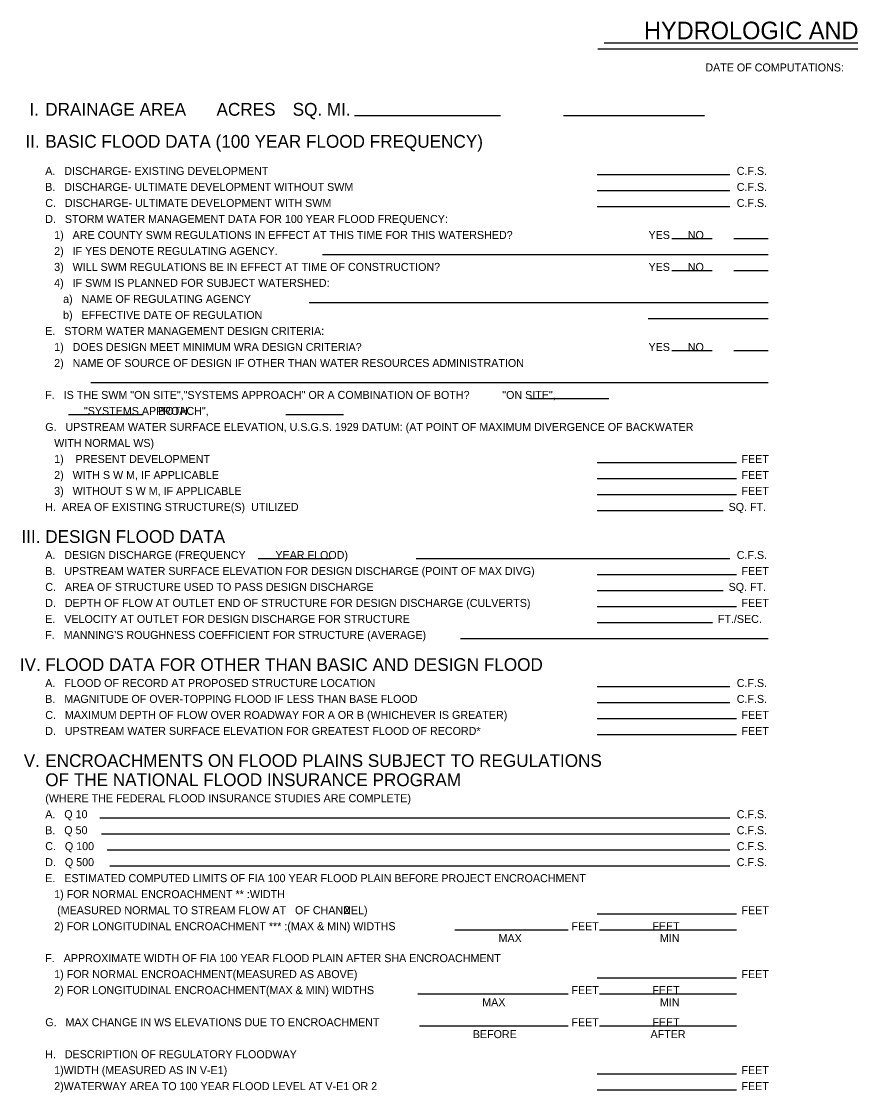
# Model space of a CAD drawing. Extents: x 3 to 31.3, y 2.1 to 20.5.
# Drawn here: x 3.01 to 13.21, y 7.36 to 20.53 of the extents above; entities that cross this region are included whole.
import ezdxf

# ---------------------------------------------------------------- set-up
doc = ezdxf.new("R2010")
doc.units = 0
doc.layers.add('G-ANNO-NOTE', color=7, linetype='Continuous')

msp = doc.modelspace()

# ---------------------------------------------------------------- linework, layer by layer
at = {"layer": 'G-ANNO-NOTE'}
for p, q in [((10.1, 20.198), (16.402, 20.198)), ((10.178, 20.27), (16.33, 20.27)), ((8.903, 19.374), (7.107, 19.374)), ((11.411, 19.374), (9.677, 19.374)), ((11.721, 18.646), (10.09, 18.646)), ((11.721, 18.449), (10.09, 18.449)), ((11.721, 18.252), (10.09, 18.252)), ((11.504, 17.858), (11.008, 17.858)), ((12.193, 17.858), (11.772, 17.858)), ((12.193, 17.661), (6.714, 17.661)), ((11.504, 17.465), (11.008, 17.465)), ((12.193, 17.465), (11.772, 17.465)), ((12.193, 17.071), (6.549, 17.071)), ((12.193, 16.874), (10.719, 16.874)), ((11.504, 16.48), (11.008, 16.48)), ((12.193, 16.48), (11.772, 16.48)), ((12.193, 16.087), (3.865, 16.087)), ((10.234, 15.89), (9.264, 15.89)), ((4.505, 15.693), (3.587, 15.693)), ((6.972, 15.693), (6.26, 15.693)), ((11.803, 15.102), (10.09, 15.102)), ((11.803, 14.905), (10.09, 14.905)), ((11.803, 14.709), (10.09, 14.709)), ((11.638, 14.512), (10.09, 14.512)), ((6.815, 13.921), (5.922, 13.921)), ((11.721, 13.921), (7.864, 13.921)), ((11.803, 13.724), (10.09, 13.724)), ((11.638, 13.528), (10.09, 13.528)), ((11.803, 13.331), (10.09, 13.331)), ((11.507, 13.134), (10.09, 13.134)), ((12.193, 12.937), (8.41, 12.937)), ((11.721, 12.346), (10.09, 12.346)), ((11.721, 12.15), (10.09, 12.15)), ((11.803, 11.953), (10.09, 11.953)), ((11.803, 11.756), (10.09, 11.756)), ((11.721, 10.732), (3.973, 10.732)), ((11.721, 10.535), (3.996, 10.535)), ((11.721, 10.339), (4.065, 10.339)), ((11.721, 10.142), (4.099, 10.142)), ((11.803, 9.551), (10.09, 9.551)), ((9.733, 9.354), (8.34, 9.354)), ((11.803, 9.354), (10.119, 9.354)), ((11.803, 8.764), (10.09, 8.764)), ((9.733, 8.567), (7.883, 8.567)), ((11.803, 8.567), (10.119, 8.567)), ((9.733, 8.173), (7.906, 8.173)), ((11.803, 8.173), (10.119, 8.173)), ((11.803, 7.583), (10.09, 7.583)), ((11.803, 7.386), (10.09, 7.386))]:
    msp.add_line(p, q, dxfattribs=at)

# ---------------------------------------------------------------- texts
for s, height, p in [('HYDROLOGIC AND HYDRAULIC DATA', 0.21654, (10.666, 20.315)), ('DATE OF COMPUTATIONS:', 0.09843, (11.421, 19.919)), ('I.  ', 0.1575, (3.108, 19.374)), ('DRAINAGE AREA', 0.15748, (3.303, 19.374)), ('                                    ACRES', 0.15748, (3.303, 19.374)), ('                                                    SQ. MI.', 0.15748, (3.303, 19.374)), ('II.  ', 0.1575, (3.059, 18.98)), ('BASIC FLOOD DATA (100 YEAR FLOOD FREQUENCY)', 0.15748, (3.303, 18.98)), ('A.   DISCHARGE- EXISTING DEVELOPMENT', 0.09843, (3.303, 18.646)), ('C.F.S.', 0.0984, (11.807, 18.646)), ('B.   DISCHARGE- ULTIMATE DEVELOPMENT WITHOUT SWM', 0.09843, (3.303, 18.449)), ('C.F.S.', 0.0984, (11.807, 18.449)), ('C.   DISCHARGE- ULTIMATE DEVELOPMENT WITH SWM', 0.09843, (3.303, 18.252)), ('C.F.S.', 0.0984, (11.807, 18.252)), ('D.   STORM WATER MANAGEMENT DATA FOR 100 YEAR FLOOD FREQUENCY:', 0.09843, (3.303, 18.055)), ('   1)   ARE COUNTY SWM REGULATIONS IN EFFECT AT THIS TIME FOR THIS WATERSHED?', 0.09843, (3.303, 17.858)), ('YES      NO     ', 0.09843, (10.722, 17.858)), ('   2)   IF YES DENOTE REGULATING AGENCY.', 0.09843, (3.303, 17.661)), ('   3)   WILL SWM REGULATIONS BE IN EFFECT AT TIME OF CONSTRUCTION?', 0.09843, (3.303, 17.465)), ('YES      NO     ', 0.09843, (10.722, 17.465)), ('   4)   IF SWM IS PLANNED FOR SUBJECT WATERSHED:', 0.09843, (3.303, 17.268)), ('      a)   NAME OF REGULATING AGENCY', 0.09843, (3.303, 17.071)), ('      b)   EFFECTIVE DATE OF REGULATION', 0.09843, (3.303, 16.874)), ('E.   STORM WATER MANAGEMENT DESIGN CRITERIA:', 0.09843, (3.303, 16.677)), ('   1)   DOES DESIGN MEET MINIMUM WRA DESIGN CRITERIA?', 0.09843, (3.303, 16.48)), ('YES      NO     ', 0.09843, (10.722, 16.48)), ('   2)   NAME OF SOURCE OF DESIGN IF OTHER THAN WATER RESOURCES ADMINISTRATION', 0.09843, (3.303, 16.283)), ('F.   IS THE SWM "ON SITE","SYSTEMS APPROACH" OR A COMBINATION OF BOTH?           "ON SITE",', 0.09843, (3.303, 15.89)), ('             "SYSTEMS APPROACH",', 0.09843, (3.303, 15.693)), ('                                      BOTH.', 0.09843, (3.303, 15.693)), ('G.   UPSTREAM WATER SURFACE ELEVATION, U.S.G.S. 1929 DATUM: (AT POINT OF MAXIMUM DIVERGENCE OF BACKWATER', 0.098425, (3.303, 15.496)), ('   WITH NORMAL WS)', 0.09843, (3.303, 15.299)), ('   1)    PRESENT DEVELOPMENT', 0.09843, (3.303, 15.102)), ('FEET', 0.0984, (11.865, 15.102)), ('   2)   WITH S W M, IF APPLICABLE', 0.09843, (3.303, 14.905)), ('FEET', 0.0984, (11.865, 14.905)), ('   3)   WITHOUT S W M, IF APPLICABLE', 0.09843, (3.303, 14.709)), ('FEET', 0.0984, (11.865, 14.709)), ('H.  AREA OF EXISTING STRUCTURE(S)  UTILIZED', 0.09843, (3.303, 14.512)), ('SQ. FT.', 0.0984, (11.707, 14.512)), ('III.  ', 0.1575, (3.01, 14.118)), ('DESIGN FLOOD DATA', 0.15748, (3.303, 14.118)), ('A.   DESIGN DISCHARGE (FREQUENCY          YEAR FLOOD)', 0.09843, (3.303, 13.921)), ('C.F.S.', 0.0984, (11.807, 13.921)), ('B.   UPSTREAM WATER SURFACE ELEVATION FOR DESIGN DISCHARGE (POINT OF MAX DIVG)', 0.09843, (3.303, 13.724)), ('FEET', 0.0984, (11.865, 13.724)), ('C.   AREA OF STRUCTURE USED TO PASS DESIGN DISCHARGE', 0.09843, (3.303, 13.528)), ('SQ. FT.', 0.0984, (11.707, 13.528)), ('D.   DEPTH OF FLOW AT OUTLET END OF STRUCTURE FOR DESIGN DISCHARGE (CULVERTS)', 0.09843, (3.303, 13.331)), ('FEET', 0.0984, (11.865, 13.331)), ('E.   VELOCITY AT OUTLET FOR DESIGN DISCHARGE FOR STRUCTURE', 0.09843, (3.303, 13.134)), ('FT./SEC.', 0.0984, (11.575, 13.134)), ("F.   MANNING'S ROUGHNESS COEFFICIENT FOR STRUCTURE (AVERAGE)", 0.09843, (3.303, 12.937)), ('IV.  ', 0.1575, (2.99, 12.543)), ('FLOOD DATA FOR OTHER THAN BASIC AND DESIGN FLOOD', 0.15748, (3.303, 12.543)), ('A.   FLOOD OF RECORD AT PROPOSED STRUCTURE LOCATION', 0.09843, (3.303, 12.346)), ('C.F.S.', 0.0984, (11.807, 12.346)), ('B.   MAGNITUDE OF OVER-TOPPING FLOOD IF LESS THAN BASE FLOOD', 0.09843, (3.303, 12.15)), ('C.F.S.', 0.0984, (11.807, 12.15)), ('C.   MAXIMUM DEPTH OF FLOW OVER ROADWAY FOR A OR B (WHICHEVER IS GREATER)', 0.09843, (3.303, 11.953)), ('FEET', 0.0984, (11.865, 11.953)), ('D.   UPSTREAM WATER SURFACE ELEVATION FOR GREATEST FLOOD OF RECORD*', 0.09843, (3.303, 11.756)), ('FEET', 0.0984, (11.865, 11.756)), ('V.  ', 0.1575, (3.039, 11.362)), ('ENCROACHMENTS ON FLOOD PLAINS SUBJECT TO REGULATIONS', 0.15748, (3.303, 11.362)), ('OF THE NATIONAL FLOOD INSURANCE PROGRAM', 0.15748, (3.303, 11.126)), ('(WHERE THE FEDERAL FLOOD INSURANCE STUDIES ARE COMPLETE)', 0.09843, (3.303, 10.929)), ('A.   Q 10', 0.0984, (3.303, 10.732)), ('C.F.S.', 0.0984, (11.807, 10.732)), ('B.   Q 50', 0.0984, (3.303, 10.535)), ('C.F.S.', 0.0984, (11.807, 10.535)), ('C.   Q 100', 0.0984, (3.303, 10.339)), ('C.F.S.', 0.0984, (11.807, 10.339)), ('D.   Q 500', 0.0984, (3.303, 10.142)), ('C.F.S.', 0.0984, (11.807, 10.142)), ('E.   ESTIMATED COMPUTED LIMITS OF FIA 100 YEAR FLOOD PLAIN BEFORE PROJECT ENCROACHMENT', 0.09843, (3.303, 9.945)), ('   1) FOR NORMAL ENCROACHMENT ** :WIDTH', 0.09843, (3.303, 9.748)), ('    (MEASURED NORMAL TO STREAM FLOW AT   OF CHANNEL)', 0.09843, (3.303, 9.551)), ('2', 0.0984, (6.974, 9.554)), ('FEET', 0.0984, (11.865, 9.551)), ('   2) FOR LONGITUDINAL ENCROACHMENT *** :(MAX & MIN) WIDTHS', 0.09843, (3.303, 9.354)), ('FEET                  FEET', 0.09843, (9.774, 9.354)), ('MAX', 0.0984, (8.878, 9.207)), ('MIN', 0.0984, (10.862, 9.207)), ('F.   APPROXIMATE WIDTH OF FIA 100 YEAR FLOOD PLAIN AFTER SHA ENCROACHMENT', 0.09843, (3.303, 8.961)), ('   1) FOR NORMAL ENCROACHMENT(MEASURED AS ABOVE)', 0.09843, (3.303, 8.764)), ('FEET', 0.0984, (11.865, 8.764)), ('   2) FOR LONGITUDINAL ENCROACHMENT(MAX & MIN) WIDTHS', 0.09843, (3.303, 8.567)), ('FEET                  FEET', 0.09843, (9.774, 8.567)), ('MAX', 0.0984, (8.677, 8.419)), ('MIN', 0.0984, (10.862, 8.419)), ('G.   MAX CHANGE IN WS ELEVATIONS DUE TO ENCROACHMENT', 0.09843, (3.303, 8.173)), ('FEET                  FEET', 0.09843, (9.774, 8.173)), ('BEFORE', 0.0984, (8.561, 8.026)), ('AFTER', 0.0984, (10.747, 8.026)), ('H.   DESCRIPTION OF REGULATORY FLOODWAY', 0.09843, (3.303, 7.779)), ('   1)WIDTH (MEASURED AS IN V-E1)', 0.09843, (3.303, 7.583)), ('FEET', 0.0984, (11.865, 7.583)), ('   2)WATERWAY AREA TO 100 YEAR FLOOD LEVEL AT V-E1 OR 2', 0.09843, (3.303, 7.386)), ('FEET', 0.0984, (11.865, 7.386))]:
    msp.add_text(s, height=height, dxfattribs=at).set_placement(p)

doc.saveas('drawing.dxf')
